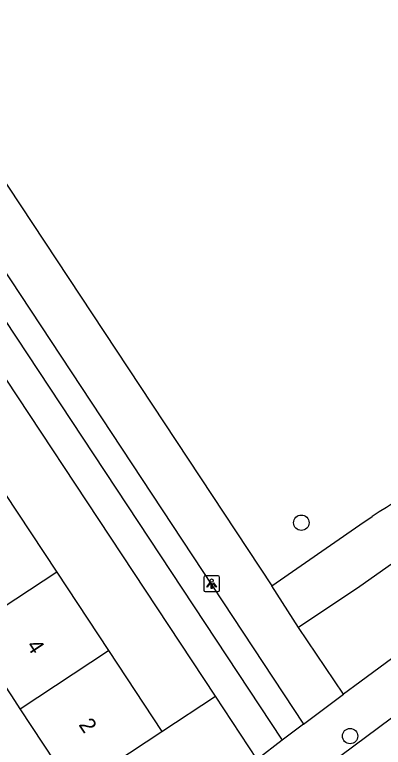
# Model space of a CAD drawing. Extents: x 160037 to 160839, y 385326 to 386441.
# Drawn here: x 160478.11 to 160501.48, y 385846.89 to 385893.36 of the extents above; entities that cross this region are included whole.
import ezdxf

# ---------------------------------------------------------------- set-up
doc = ezdxf.new("R2010")
doc.units = 0
for name, color, linetype in [('IMGEO_Boom', 7, 'Continuous'), ('IMGEO_Groenvoorziening', 7, 'Continuous'), ('IMGEO_Lichtpunt', 7, 'Continuous'), ('IMGEO_Pand', 7, 'Continuous'), ('IMGEO_Pand_nummerreeks', 7, 'Continuous'), ('IMGEO_Rijbaan_lokaal_gesloten', 7, 'Continuous'), ('IMGEO_Voetpad_open', 7, 'Continuous')]:
    doc.layers.add(name, color=color, linetype=linetype)

msp = doc.modelspace()

# ---------------------------------------------------------------- linework, layer by layer
at = {"layer": 'IMGEO_Boom'}
for centre in [(160496.283, 385861.138), (160499.377, 385847.602)]:
    msp.add_circle(centre, 0.489, dxfattribs=at)
at = {"layer": 'IMGEO_Groenvoorziening'}
for points in [[(160472.553, 385881.429), (160495.073, 385847.335)], [(160490.841, 385850.132), (160470.884, 385880.328)], [(160487.444, 385847.892), (160490.841, 385850.132)], [(160493.476, 385846.124), (160490.841, 385850.132)]]:
    msp.add_lwpolyline(points, dxfattribs=at)
at = {"layer": 'IMGEO_Lichtpunt'}
for p, q in [((160490.099, 385857.67), (160490.099, 385856.863)), ((160490.099, 385857.67), (160490.099, 385856.863)), ((160491.001, 385857.765), (160490.193, 385857.765)), ((160491.001, 385857.765), (160490.193, 385857.765)), ((160491.095, 385856.863), (160491.095, 385857.67)), ((160491.095, 385856.863), (160491.095, 385857.67)), ((160490.193, 385856.769), (160491.001, 385856.769)), ((160490.193, 385856.769), (160491.001, 385856.769))]:
    msp.add_line(p, q, dxfattribs=at)
for points in [[(160490.473, 385857.334), (160490.512, 385857.306), (160490.324, 385857.044), (160490.286, 385857.071), (160490.473, 385857.334)], [(160490.575, 385857.286), (160490.622, 385857.286), (160490.622, 385856.964), (160490.575, 385856.964), (160490.575, 385857.286)], [(160490.685, 385857.306), (160490.723, 385857.333), (160490.91, 385857.071), (160490.871, 385857.043), (160490.685, 385857.306)]]:
    msp.add_lwpolyline(points, dxfattribs=at)
msp.add_circle((160490.598, 385857.468), 0.0994, dxfattribs=at)
for centre, start, end in [((160490.193, 385857.67), 90, 180), ((160490.193, 385857.67), 90, 180), ((160491.001, 385857.67), 0, 90), ((160491.001, 385857.67), 0, 90), ((160490.193, 385856.863), 180, 270), ((160490.193, 385856.863), 180, 270), ((160491.001, 385856.863), 270, 0), ((160491.001, 385856.863), 270, 360)]:
    msp.add_arc(centre, 0.0946, start, end, dxfattribs=at)
at = {"layer": 'IMGEO_Pand'}
for points in [[(160477.482, 385863), (160480.772, 385858.011)], [(160480.772, 385858.011), (160474.642, 385853.969)], [(160480.772, 385858.011), (160484.06, 385853.023)], [(160478.461, 385849.331), (160477.923, 385850.146), (160476.365, 385852.508), (160475.835, 385852.159), (160474.642, 385853.969)], [(160478.461, 385849.331), (160484.06, 385853.023)], [(160484.06, 385853.023), (160487.444, 385847.892)], [(160481.363, 385843.883), (160480.195, 385845.654), (160480.676, 385845.972), (160478.461, 385849.331)], [(160481.363, 385843.883), (160487.444, 385847.892)]]:
    msp.add_lwpolyline(points, dxfattribs=at)
at = {"layer": 'IMGEO_Rijbaan_lokaal_gesloten'}
msp.add_lwpolyline([(160493.352, 385842.337), (160502.735, 385849.311), (160511.134, 385854.977), (160512.487, 385855.591)], dxfattribs=at)
at = {"layer": 'IMGEO_Voetpad_open'}
for points in [[(160462.447, 385896.161), (160470.862, 385892.763), (160494.405, 385857.131)], [(160473.981, 385882.371), (160496.43, 385848.363)], [(160494.405, 385857.131), (160500, 385860.998), (160500.778, 385861.535)], [(160503.797, 385859.782), (160500, 385857.085), (160496.106, 385854.494)], [(160496.106, 385854.494), (160494.405, 385857.131)], [(160498.965, 385850.262), (160496.106, 385854.494)], [(160502.491, 385852.872), (160500, 385851.029), (160498.965, 385850.262)], [(160496.43, 385848.363), (160498.965, 385850.262)], [(160496.43, 385848.363), (160495.073, 385847.335)], [(160495.073, 385847.335), (160493.476, 385846.124)]]:
    msp.add_lwpolyline(points, dxfattribs=at)
msp.add_arc((160567.092, 385758.329), 122.675, 114.71203, 122.72236, dxfattribs=at)

# ---------------------------------------------------------------- texts
at = {"layer": 'IMGEO_Pand_nummerreeks'}
for s, p in [('4', (160478.82, 385853.338)), ('2', (160482.135, 385848.327))]:
    msp.add_text(s, height=1, rotation=303.4937, dxfattribs=at).set_placement(p)

doc.saveas('drawing.dxf')
